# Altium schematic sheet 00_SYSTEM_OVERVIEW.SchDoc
size 840 x 594 mm
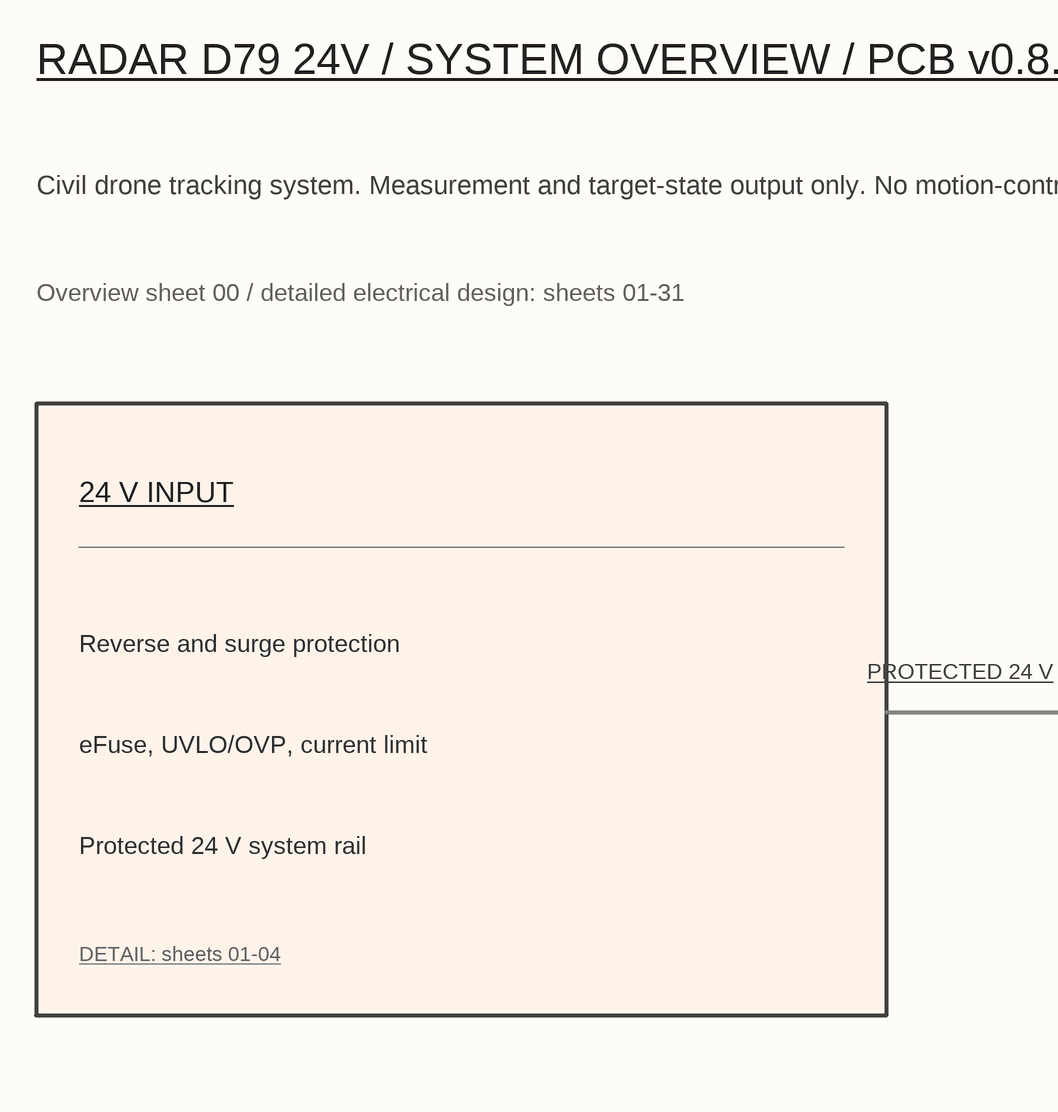
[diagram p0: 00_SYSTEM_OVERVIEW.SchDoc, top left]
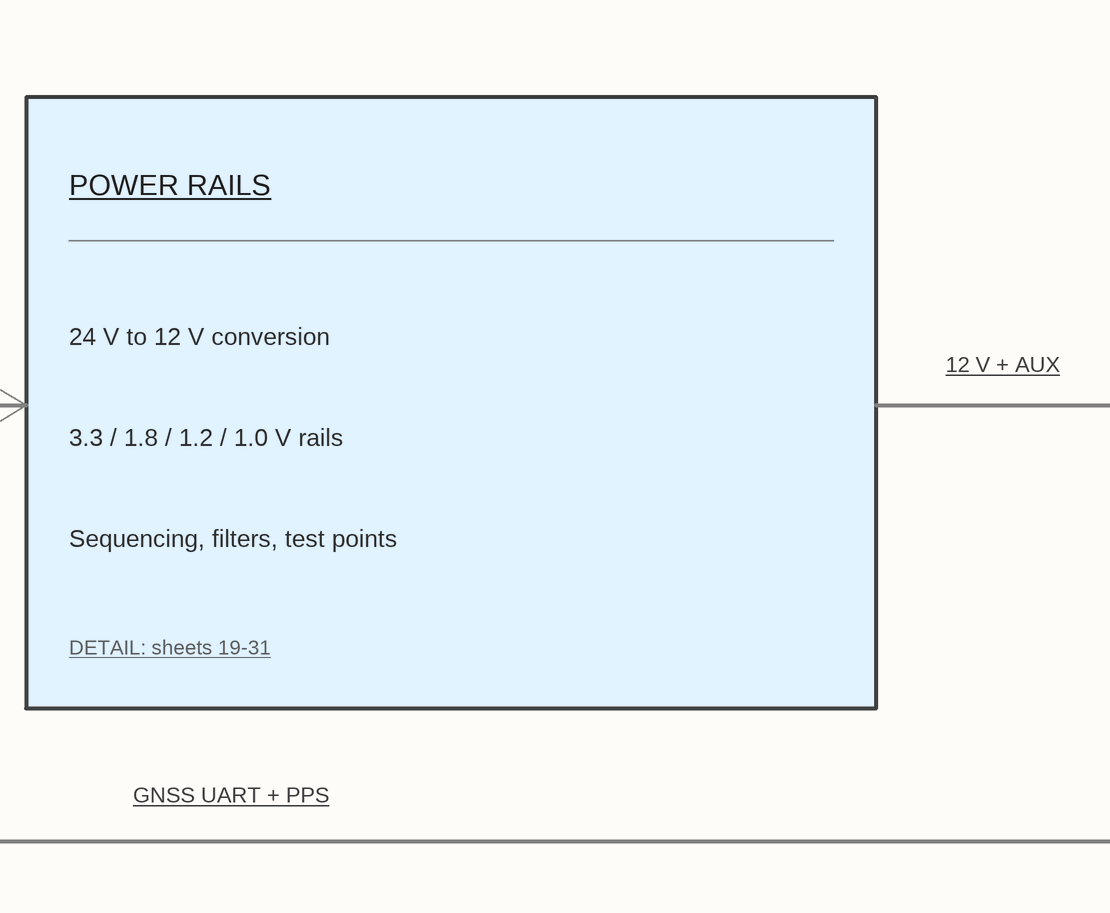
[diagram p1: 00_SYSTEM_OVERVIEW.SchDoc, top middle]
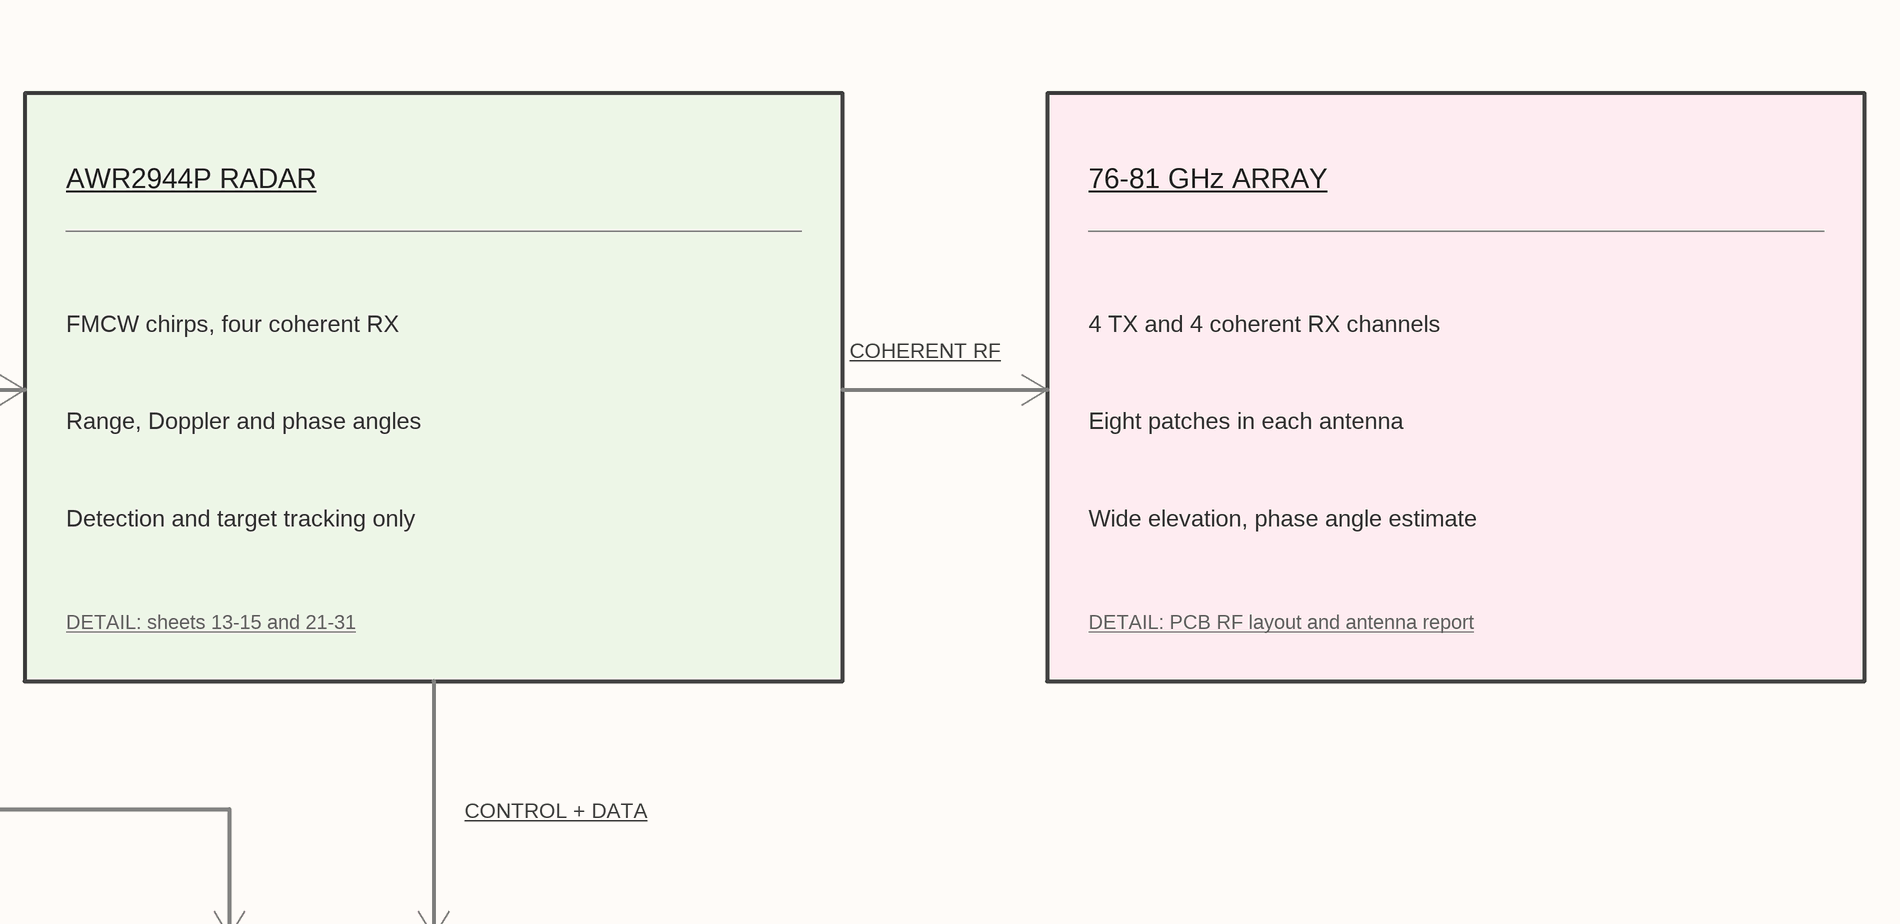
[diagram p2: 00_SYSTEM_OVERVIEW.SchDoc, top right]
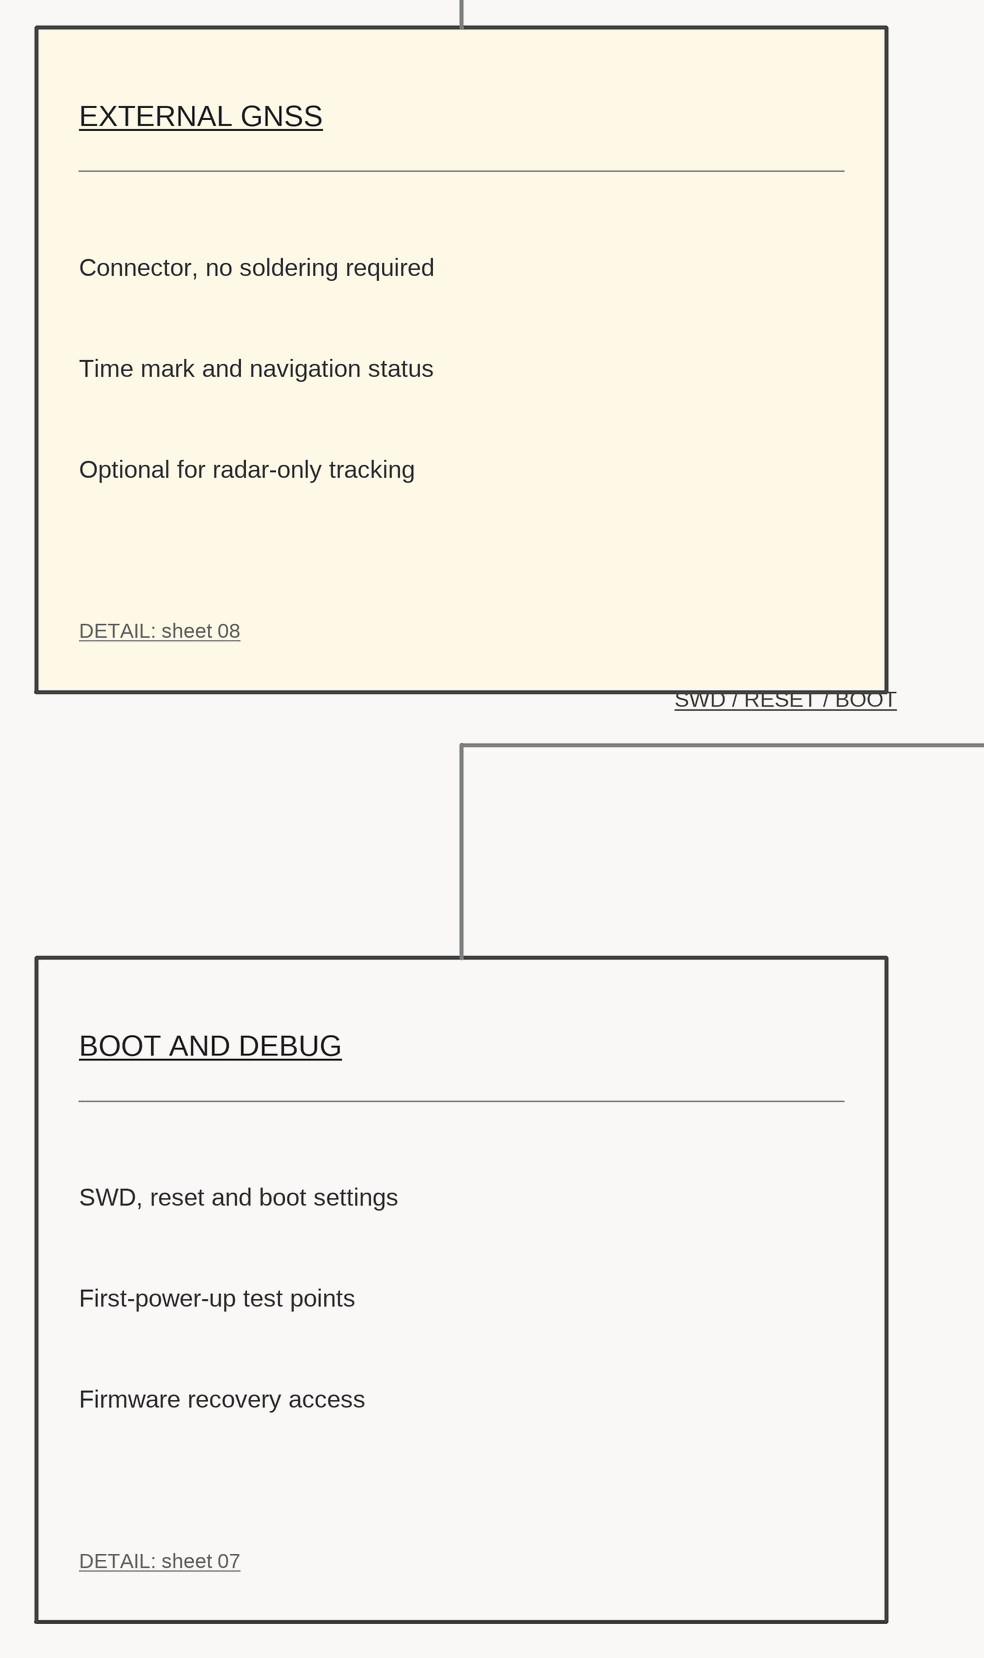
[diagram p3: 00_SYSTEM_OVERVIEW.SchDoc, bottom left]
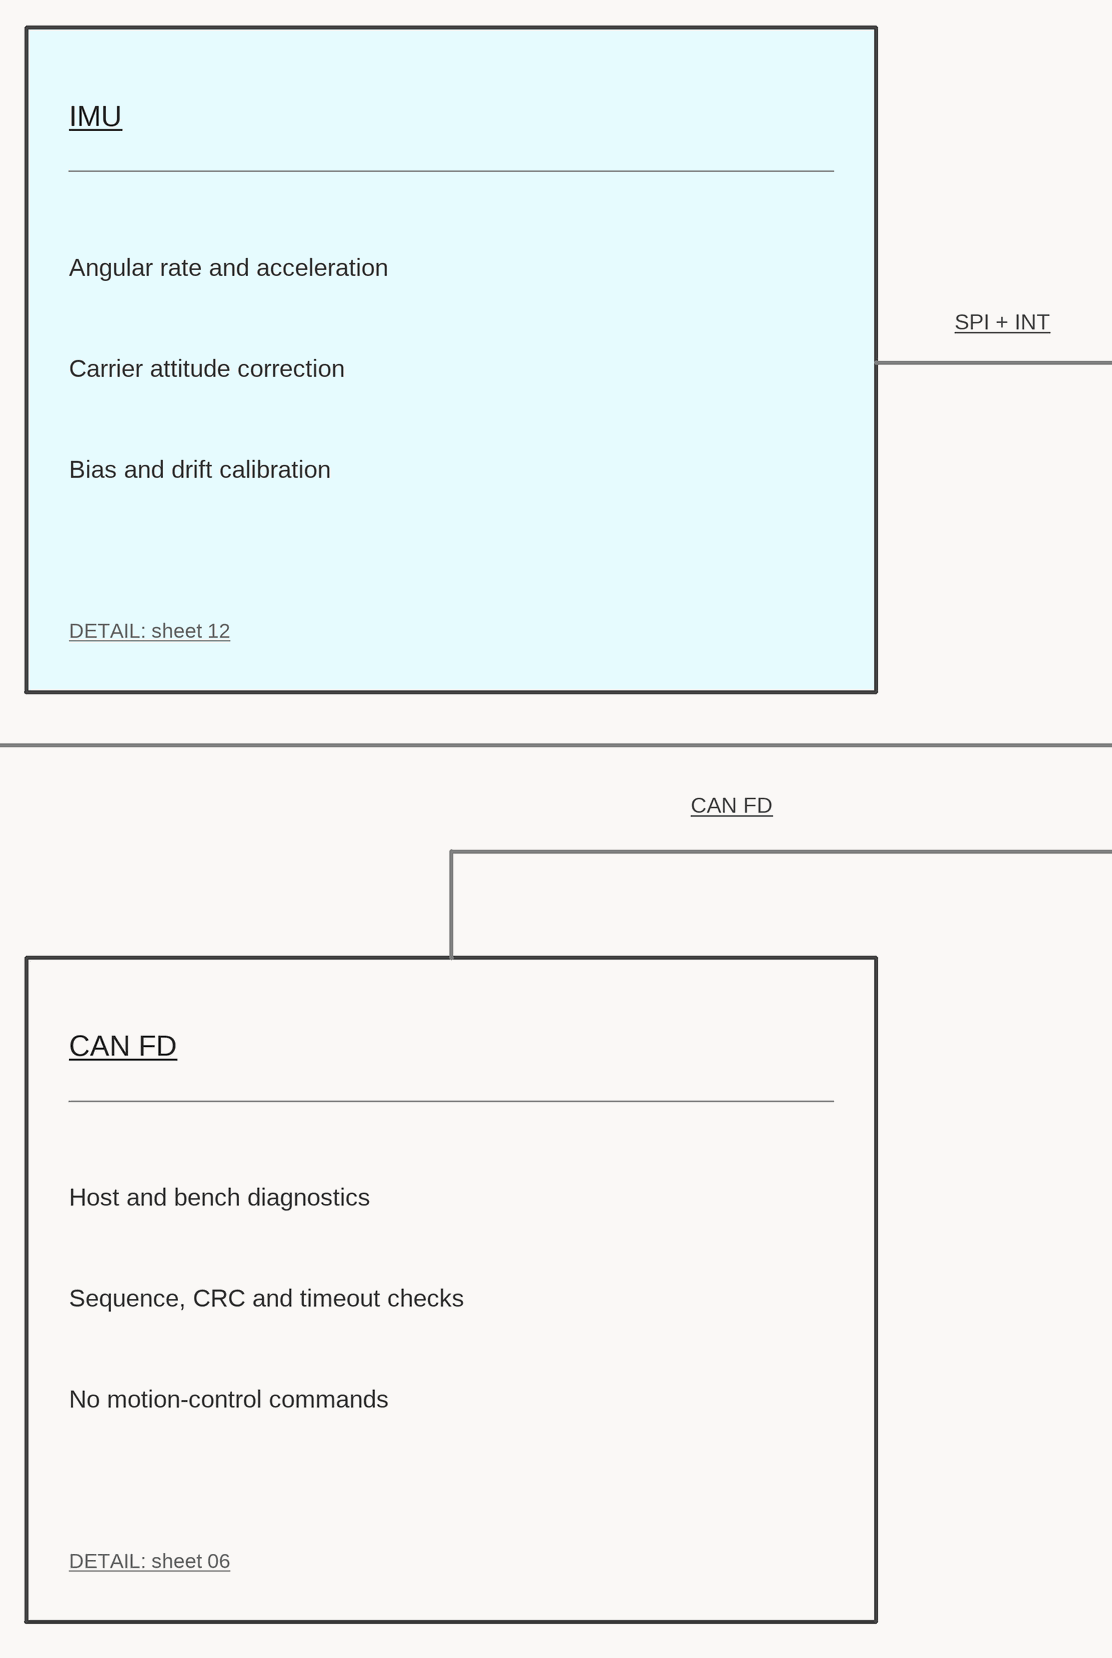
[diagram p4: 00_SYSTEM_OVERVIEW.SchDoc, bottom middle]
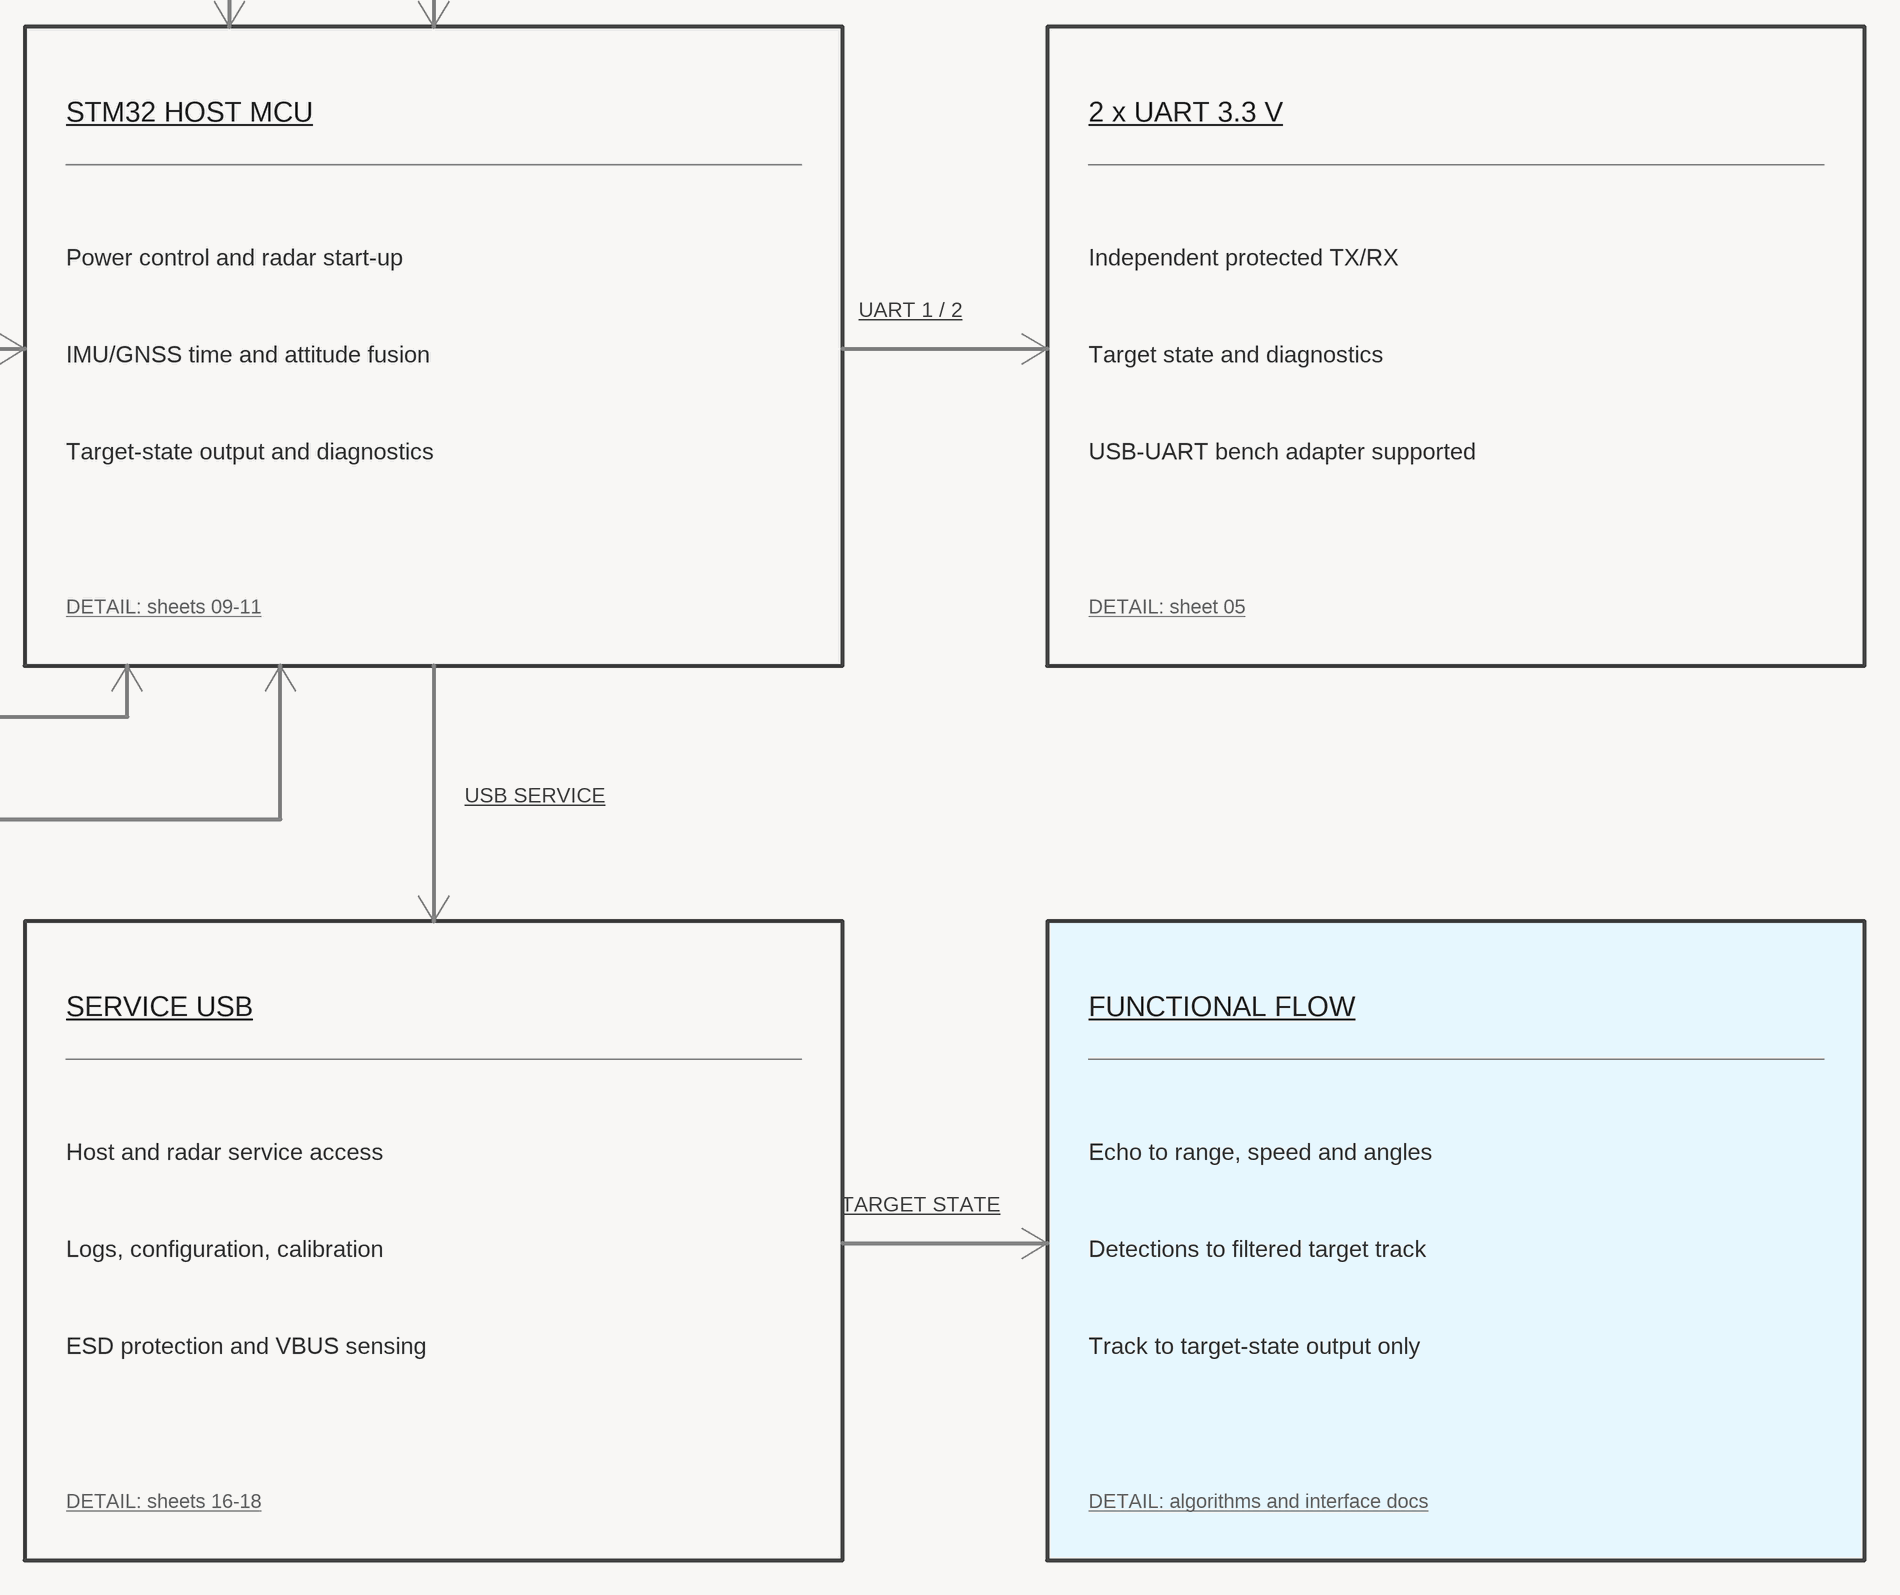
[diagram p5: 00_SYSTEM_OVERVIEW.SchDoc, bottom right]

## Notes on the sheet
- RADAR D79 24V / SYSTEM OVERVIEW / PCB v0.8.0 R9
- Civil drone tracking system. Measurement and target-state output only. No motion-control commands.
- Overview sheet 00 / detailed electrical design: sheets 01-31
- 24 V INPUT
- POWER RAILS
- AWR2944P RADAR
- 76-81 GHz ARRAY
- Reverse and surge protection
- PROTECTED 24 V
- 24 V to 12 V conversion
- 12 V + AUX
- FMCW chirps, four coherent RX
- COHERENT RF
- 4 TX and 4 coherent RX channels
- eFuse, UVLO/OVP, current limit
- 3.3 / 1.8 / 1.2 / 1.0 V rails
- Range, Doppler and phase angles
- Eight patches in each antenna
- Protected 24 V system rail
- Sequencing, filters, test points
- Detection and target tracking only
- Wide elevation, phase angle estimate
- DETAIL: sheets 01-04
- DETAIL: sheets 19-31
- DETAIL: sheets 13-15 and 21-31
- DETAIL: PCB RF layout and antenna report
- GNSS UART + PPS
- CONTROL + DATA
- EXTERNAL GNSS
- IMU
- STM32 HOST MCU
- 2 x UART 3.3 V
- Connector, no soldering required
- Angular rate and acceleration
- SPI + INT
- Power control and radar start-up
- UART 1 / 2
- Independent protected TX/RX
- Time mark and navigation status
- Carrier attitude correction
- IMU/GNSS time and attitude fusion
- Target state and diagnostics
- Optional for radar-only tracking
- Bias and drift calibration
- Target-state output and diagnostics
- USB-UART bench adapter supported
- DETAIL: sheet 08
- DETAIL: sheet 12
- DETAIL: sheets 09-11
- DETAIL: sheet 05
- SWD / RESET / BOOT
- CAN FD
- USB SERVICE
- BOOT AND DEBUG
- SERVICE USB
- FUNCTIONAL FLOW
- SWD, reset and boot settings
- Host and bench diagnostics
- Host and radar service access
- Echo to range, speed and angles
- TARGET STATE
- First-power-up test points
- Sequence, CRC and timeout checks
- Logs, configuration, calibration
- Detections to filtered target track
- Firmware recovery access
- No motion-control commands
- ESD protection and VBUS sensing
- Track to target-state output only
- DETAIL: sheet 07
- DETAIL: sheet 06
- DETAIL: sheets 16-18
- DETAIL: algorithms and interface docs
